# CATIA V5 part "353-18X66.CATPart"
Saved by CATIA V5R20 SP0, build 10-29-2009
Part number: 353-18X66
Definition: NONE
Nomenclature: 353-18X66
Source: Unknown
Description: 353-18X66
Bounding box of the stored display mesh (mm): x -5 to 61, y -15 to 15, z -15 to 15
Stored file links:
  C:\Users\Utente\Desktop\IO LAVORO\3D X SITO CF\X SITO\PLASTICA\353\353-18X66.CATPart
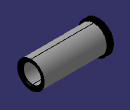
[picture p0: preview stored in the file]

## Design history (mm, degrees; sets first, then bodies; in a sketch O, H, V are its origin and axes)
Body1 "353-18X66" (main body)
  Solid1: solid without history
